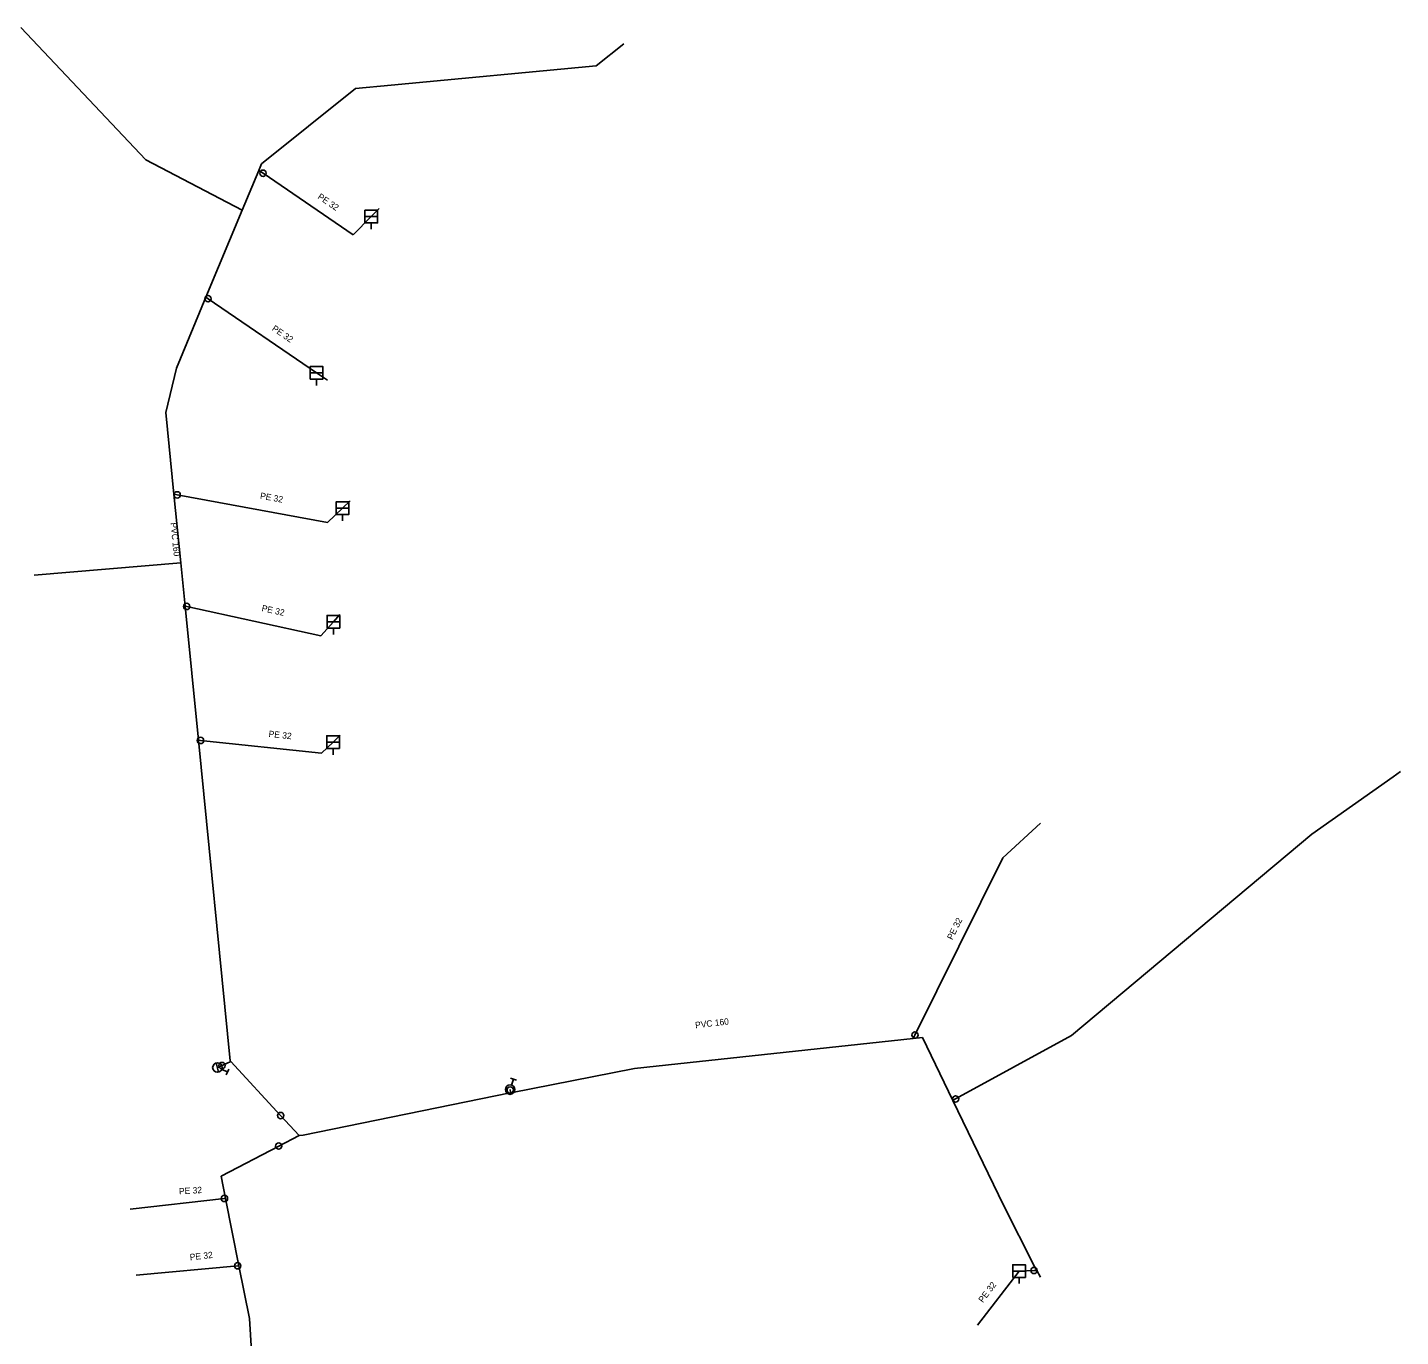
# Model space of a CAD drawing. Extents: x -725126 to -724740, y -1049524 to -1048684.
# Drawn here: x -724956.6 to -724739.5, y -1048937.4 to -1048730.4 of the extents above; entities that cross this region are included whole.
import ezdxf

# ---------------------------------------------------------------- set-up
doc = ezdxf.new("R2010")
doc.units = 0
doc.layers.add('Level 0', color=7, linetype='Continuous')

msp = doc.modelspace()

# ---------------------------------------------------------------- linework, layer by layer
at = {"layer": 'Level 0'}
for p, q in [((-724937.88, -1048751.38), (-724957.64, -1048730.44)), ((-724866.68, -1048736.48), (-724862.33, -1048733.01)), ((-724899.09, -1048739.56), (-724866.68, -1048736.48)), ((-724919.57, -1048752.02), (-724904.72, -1048740.09)), ((-724904.72, -1048740.09), (-724899.09, -1048739.56)), ((-724922.62, -1048759.32), (-724937.88, -1048751.38)), ((-724922.62, -1048759.32), (-724920, -1048753.04)), ((-724920, -1048753.04), (-724919.57, -1048752.02)), ((-724919.35, -1048753.48), (-724920, -1048753.04)), ((-724905.12, -1048763.2), (-724919.35, -1048753.48)), ((-724928.37, -1048773.09), (-724922.62, -1048759.32)), ((-724900.99, -1048759.07), (-724902.24, -1048760.33)), ((-724902.24, -1048760.33), (-724905.12, -1048763.2)), ((-724902.24, -1048762.33), (-724902.24, -1048761.33)), ((-724933.05, -1048784.28), (-724928.37, -1048773.09)), ((-724928.04, -1048773.31), (-724928.37, -1048773.09)), ((-724910.88, -1048785.03), (-724928.04, -1048773.31)), ((-724934.71, -1048791.32), (-724933.05, -1048784.28)), ((-724909.16, -1048786.21), (-724910.88, -1048785.03)), ((-724910.88, -1048787.03), (-724910.88, -1048786.03)), ((-724933.43, -1048804.23), (-724934.71, -1048791.32)), ((-724932.92, -1048804.32), (-724933.43, -1048804.23)), ((-724932.35, -1048815.05), (-724933.43, -1048804.23)), ((-724909.16, -1048808.68), (-724932.92, -1048804.32)), ((-724905.57, -1048805.27), (-724906.76, -1048806.41)), ((-724906.76, -1048806.41), (-724909.16, -1048808.68)), ((-724906.76, -1048808.41), (-724906.76, -1048807.41)), ((-724955.53, -1048817.01), (-724932.35, -1048815.05)), ((-724931.67, -1048821.91), (-724932.35, -1048815.05)), ((-724931.41, -1048821.96), (-724931.67, -1048821.91)), ((-724929.57, -1048843.11), (-724931.67, -1048821.91)), ((-724910.19, -1048826.58), (-724931.41, -1048821.96)), ((-724908.23, -1048824.38), (-724910.19, -1048826.58)), ((-724907.23, -1048823.25), (-724908.23, -1048824.38)), ((-724908.23, -1048826.38), (-724908.23, -1048825.38)), ((-724907.14, -1048842.29), (-724908.27, -1048843.39)), ((-724929.24, -1048843.14), (-724929.57, -1048843.11)), ((-724924.55, -1048893.77), (-724929.57, -1048843.11)), ((-724910.1, -1048845.17), (-724929.24, -1048843.14)), ((-724908.27, -1048843.39), (-724910.1, -1048845.17)), ((-724908.27, -1048845.39), (-724908.27, -1048844.39)), ((-724739.53, -1048848.04), (-724740.7, -1048848.87)), ((-724740.7, -1048848.87), (-724753.54, -1048857.93)), ((-724796.47, -1048856.21), (-724802.39, -1048861.71)), ((-724753.54, -1048857.93), (-724791.52, -1048889.75)), ((-724802.39, -1048861.71), (-724816.29, -1048889.71)), ((-724816.29, -1048889.71), (-724816.56, -1048890.27)), ((-724791.52, -1048889.75), (-724809.86, -1048899.8)), ((-724816.56, -1048890.27), (-724860.6, -1048895)), ((-724815.11, -1048890.11), (-724816.56, -1048890.27)), ((-724810.28, -1048900.03), (-724815.11, -1048890.11)), ((-724926.75, -1048894.12), (-724926.37, -1048895.57)), ((-724924.43, -1048893.9), (-724925.83, -1048894.52)), ((-724924.43, -1048893.9), (-724924.55, -1048893.77)), ((-724916.56, -1048902.43), (-724924.43, -1048893.9)), ((-724925.83, -1048894.52), (-724926.56, -1048894.84)), ((-724925.87, -1048895.14), (-724924.96, -1048895.54)), ((-724924.76, -1048895.08), (-724925.16, -1048896)), ((-724880.21, -1048896.51), (-724879.26, -1048896.83)), ((-724860.6, -1048895), (-724880.15, -1048898.84)), ((-724880.27, -1048898.39), (-724880.29, -1048898.33)), ((-724880.15, -1048898.84), (-724880.27, -1048898.39)), ((-724880.05, -1048897.62), (-724879.74, -1048896.67)), ((-724880.26, -1048898.86), (-724912.98, -1048905.51)), ((-724809.86, -1048899.8), (-724810.28, -1048900.03)), ((-724802.3, -1048916.6), (-724810.28, -1048900.03)), ((-724913.66, -1048905.58), (-724916.56, -1048902.43)), ((-724916.87, -1048907.25), (-724925.98, -1048912.01)), ((-724913.66, -1048905.58), (-724916.87, -1048907.25)), ((-724912.98, -1048905.51), (-724913.66, -1048905.58)), ((-724925.98, -1048912.01), (-724925.28, -1048915.52)), ((-724940.34, -1048917.23), (-724925.44, -1048915.53)), ((-724925.44, -1048915.53), (-724925.28, -1048915.52)), ((-724925.28, -1048915.52), (-724923.16, -1048926.16)), ((-724797.37, -1048926.29), (-724802.3, -1048916.6)), ((-724939.38, -1048927.67), (-724923.35, -1048926.18)), ((-724923.35, -1048926.18), (-724923.16, -1048926.16)), ((-724923.16, -1048926.16), (-724921.5, -1048934.52)), ((-724799.83, -1048927), (-724797.46, -1048926.92)), ((-724797.46, -1048926.92), (-724797.03, -1048926.9)), ((-724797.03, -1048926.9), (-724797.37, -1048926.29)), ((-724796.43, -1048927.96), (-724797.03, -1048926.9)), ((-724806.39, -1048935.57), (-724799.83, -1048927)), ((-724799.83, -1048929), (-724799.83, -1048928)), ((-724921.5, -1048934.52), (-724919.97, -1048958.36))]:
    msp.add_line(p, q, dxfattribs=at)
for points in [[(-724903.24, -1048760.33), (-724903.24, -1048759.33), (-724901.24, -1048759.33), (-724901.24, -1048760.33)], [(-724911.88, -1048785.03), (-724911.88, -1048784.03), (-724909.88, -1048784.03), (-724909.88, -1048785.03)], [(-724907.76, -1048806.41), (-724907.76, -1048805.41), (-724905.76, -1048805.41), (-724905.76, -1048806.41)], [(-724909.23, -1048824.38), (-724909.23, -1048823.38), (-724907.23, -1048823.38), (-724907.23, -1048824.38)], [(-724909.27, -1048843.39), (-724909.27, -1048842.39), (-724907.27, -1048842.39), (-724907.27, -1048843.39)], [(-724800.83, -1048927), (-724800.83, -1048926), (-724798.83, -1048926), (-724798.83, -1048927)]]:
    msp.add_lwpolyline(points, dxfattribs=at)
for points in [[(-724903.24, -1048761.33), (-724901.24, -1048761.33), (-724901.24, -1048760.33), (-724903.24, -1048760.33)], [(-724911.88, -1048786.03), (-724909.88, -1048786.03), (-724909.88, -1048785.03), (-724911.88, -1048785.03)], [(-724907.76, -1048807.41), (-724905.76, -1048807.41), (-724905.76, -1048806.41), (-724907.76, -1048806.41)], [(-724909.23, -1048825.38), (-724907.23, -1048825.38), (-724907.23, -1048824.38), (-724909.23, -1048824.38)], [(-724909.27, -1048844.39), (-724907.27, -1048844.39), (-724907.27, -1048843.39), (-724909.27, -1048843.39)], [(-724800.83, -1048928), (-724798.83, -1048928), (-724798.83, -1048927), (-724800.83, -1048927)]]:
    msp.add_lwpolyline(points, close=True, dxfattribs=at)
for centre, radius in [((-724919.35, -1048753.48), 0.5), ((-724928.04, -1048773.31), 0.5), ((-724932.92, -1048804.32), 0.5), ((-724931.41, -1048821.96), 0.5), ((-724929.24, -1048843.14), 0.5), ((-724816.29, -1048889.71), 0.5), ((-724926.56, -1048894.84), 0.75), ((-724925.83, -1048894.52), 0.5), ((-724880.29, -1048898.33), 0.75), ((-724880.27, -1048898.39), 0.5), ((-724809.86, -1048899.8), 0.5), ((-724916.56, -1048902.43), 0.5), ((-724916.87, -1048907.25), 0.5), ((-724925.44, -1048915.53), 0.5), ((-724923.35, -1048926.18), 0.5), ((-724797.46, -1048926.92), 0.5)]:
    msp.add_circle(centre, radius, dxfattribs=at)

# ---------------------------------------------------------------- texts
for s, rotation, p in [('PE 32', 325.664, (-724910.81, -1048757.42)), ('PE 32', 325.668, (-724918.03, -1048778.25)), ('PE 32', 349.602, (-724919.87, -1048804.91)), ('PVC 160', 275.7, (-724933.98, -1048808.74)), ('PE 32', 347.717, (-724919.63, -1048822.68)), ('PE 32', 353.946, (-724918.5, -1048842.57)), ('PE 32', 63.599, (-724810.38, -1048874.74)), ('PVC 160', 6.664, (-724850.98, -1048888.64)), ('PE 32', 3.576, (-724932.6, -1048914.9)), ('PE 32', 6.009, (-724930.87, -1048925.31)), ('PE 32', 53.09, (-724805.55, -1048932.09))]:
    msp.add_text(s, height=1, rotation=rotation, dxfattribs=at).set_placement(p)

doc.saveas('drawing.dxf')
